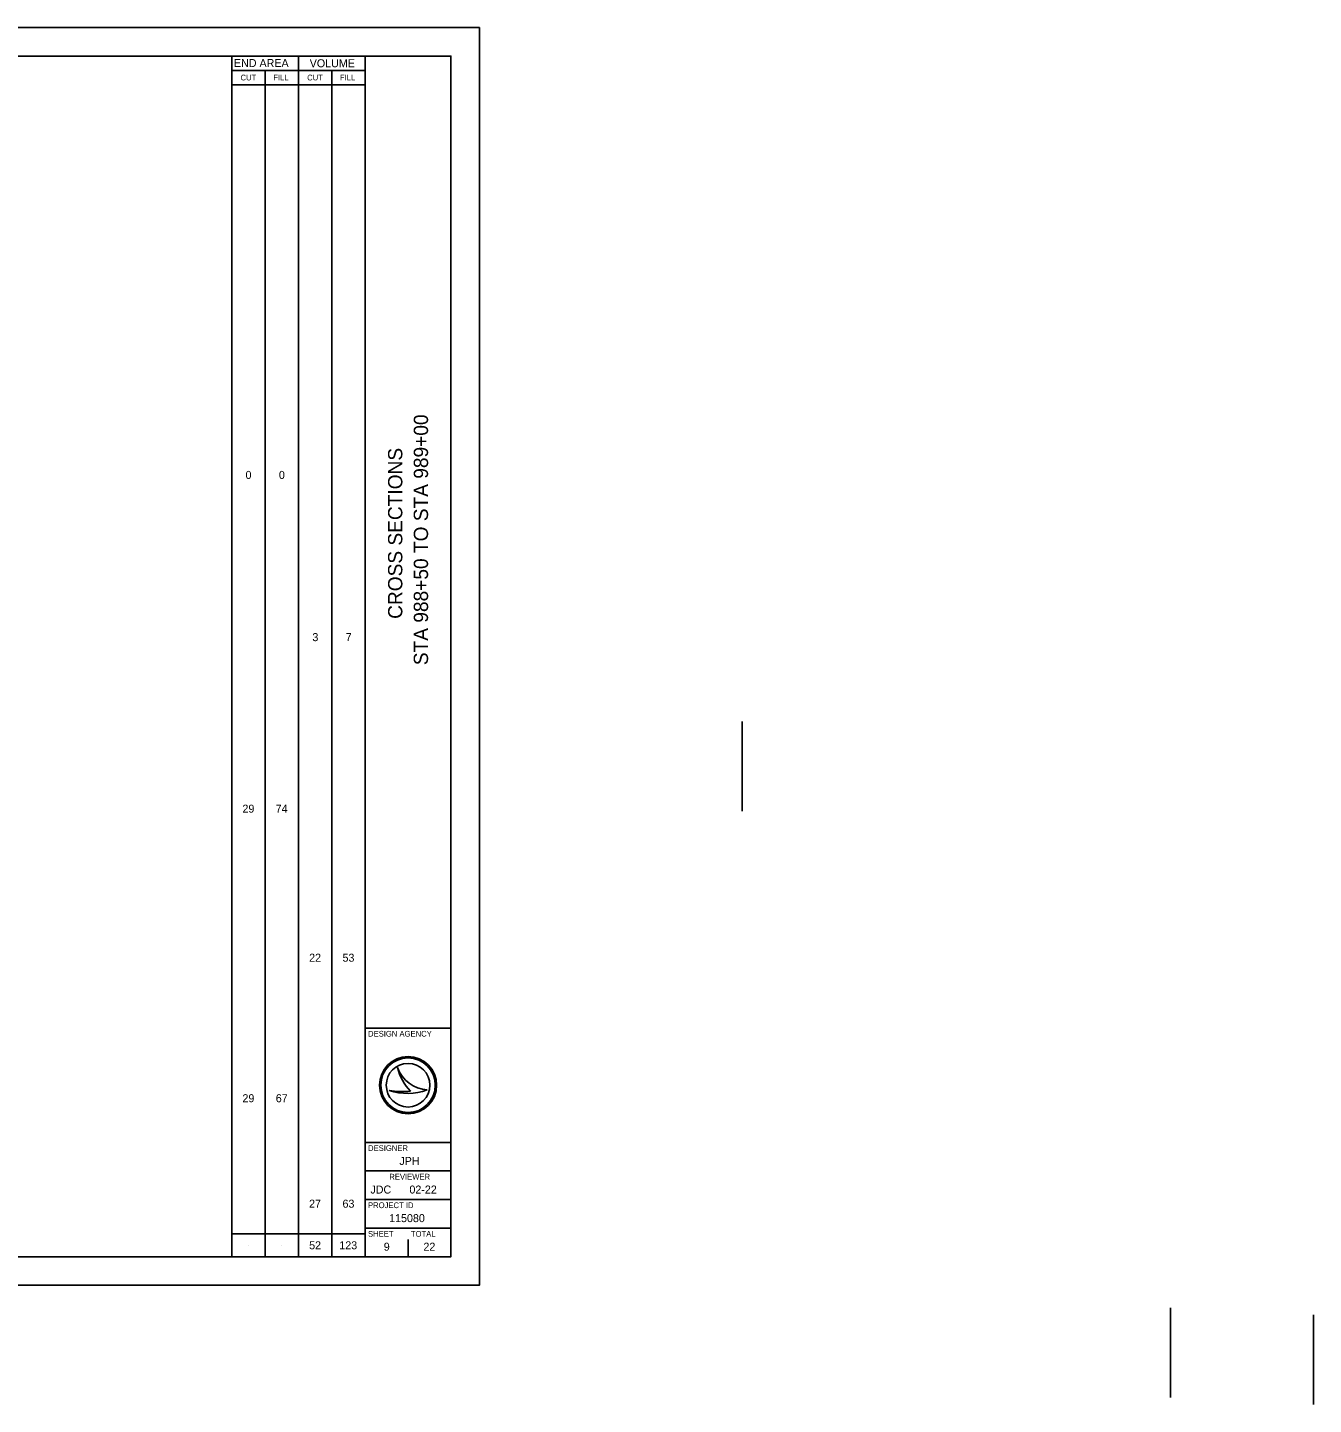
# Model space of a CAD drawing. Extents: x -41 to 232, y -116 to 22.
# Drawn here: x 26.09 to 48.59, y -2.08 to 22 of the extents above; entities that cross this region are included whole.
import ezdxf

# ---------------------------------------------------------------- set-up
doc = ezdxf.new("R2010")
doc.units = 0
for name, color, linetype in [('DT_X_Contour_Major', 7, 'Continuous'), ('DT_X_Contour_Minor', 7, 'Continuous'), ('DT_X_Contour_Text', 7, 'Continuous'), ('SH_Border', 7, 'Continuous'), ('SH_Cut_Line', 7, 'Continuous'), ('SH_Data', 7, 'Continuous'), ('SV_X_Break_Lines', 7, 'Continuous')]:
    doc.layers.add(name, color=color, linetype=linetype)

msp = doc.modelspace()

# ---------------------------------------------------------------- linework, layer by layer
at = {"layer": 'DT_X_Contour_Major'}
msp.add_line((38.594, 8.291), (38.594, 9.859), dxfattribs=at)
at = {"layer": 'DT_X_Contour_Minor'}
msp.add_line((46.094, -1.961), (46.094, -0.393), dxfattribs=at)
at = {"layer": 'DT_X_Contour_Text'}
msp.add_line((48.594, -2.084), (48.594, -0.516), dxfattribs=at)
at = {"layer": 'SH_Border'}
for p, q in [((32, 0.5), (32, 21.5)), ((32, 4.5), (33.5, 4.5)), ((32, 2.5), (33.5, 2.5)), ((32, 2), (33.5, 2)), ((32, 1.5), (33.5, 1.5)), ((32, 1), (33.5, 1))]:
    msp.add_line(p, q, dxfattribs=at)
msp.add_lwpolyline([(1.5, 21.5), (33.5, 21.5), (33.5, 0.5), (1.5, 0.5)], close=True, dxfattribs=at)
at = {"layer": 'SH_Cut_Line'}
msp.add_lwpolyline([(0, 0), (34, 0), (34, 22), (0, 22)], close=True, dxfattribs=at)
at = {"layer": 'SH_Data'}
for p, q in [((29.666, 0.5), (29.666, 21.5)), ((30.833, 0.5), (30.833, 21.5)), ((29.666, 21.25), (32, 21.25)), ((30.25, 0.5), (30.25, 21.25)), ((31.417, 0.5), (31.417, 21.25)), ((29.666, 21), (32, 21)), ((32.567, 3.81), (32.567, 3.81)), ((32.417, 3.41), (32.417, 3.41)), ((32.75, 3.5), (32.75, 3.5)), ((33.087, 3.419), (33.087, 3.419)), ((29.666, 0.9), (32, 0.9)), ((32.75, 0.5), (32.75, 0.8)), ((29.958, 0.7), (29.958, 0.7)), ((30.542, 0.7), (30.542, 0.7)), ((31.125, 0.7), (31.125, 0.7)), ((31.708, 0.7), (31.708, 0.7)), ((32.375, 0.675), (32.375, 0.675))]:
    msp.add_line(p, q, dxfattribs=at)
for radius in [0.5, 0.477, 0.477, 0.382]:
    msp.add_circle((32.75, 3.5), radius, dxfattribs=at)
for centre, radius, start, end in [((33.116, 3.998), 0.58, 198.9257, 198.9319), ((33.347, 3.97), 0.796, 191.6379, 191.6421), ((33.116, 3.998), 0.58, 198.9319, 267.1657), ((33.347, 3.97), 0.796, 191.6421, 226.0947), ((32.739, 4.37), 1.013, 251.4576, 290.0832), ((32.648, 4.654), 1.266, 259.4964, 259.4995), ((32.739, 4.37), 1.013, 251.4527, 251.4576), ((32.648, 4.654), 1.266, 259.4995, 276.6672)]:
    msp.add_arc(centre, radius, start, end, dxfattribs=at)

# ---------------------------------------------------------------- texts
for s, height, p in [('END AREA', 0.14, (29.703, 21.309)), ('VOLUME', 0.14, (31.029, 21.305)), ('CUT', 0.1, (29.819, 21.075)), ('FILL', 0.1, (30.391, 21.075)), ('CUT', 0.1, (30.985, 21.075)), ('FILL', 0.1, (31.557, 21.075)), ('DESIGN AGENCY', 0.1, (32.05, 4.35)), ('DESIGNER', 0.1, (32.05, 2.35)), ('JPH', 0.14, (32.598, 2.105)), ('REVIEWER', 0.1, (32.422, 1.85)), ('JDC', 0.14, (32.091, 1.605)), ('02-22', 0.14, (32.774, 1.605)), ('PROJECT ID', 0.1, (32.05, 1.35)), ('115080', 0.14, (32.419, 1.105)), ('SHEET', 0.1, (32.05, 0.85)), ('9', 0.14, (32.325, 0.605)), ('TOTAL', 0.1, (32.8, 0.85)), ('22', 0.14, (33.019, 0.605))]:
    msp.add_text(s, height=height, dxfattribs=at).set_placement(p)
for s, p in [('STA 988+50 TO STA 989+00', (33.1, 10.847)), ('CROSS SECTIONS', (32.65, 11.657))]:
    msp.add_text(s, height=0.25, rotation=90, dxfattribs=at).set_placement(p)
at = {"layer": 'SV_X_Break_Lines'}
for s, p in [('0', (29.906, 14.105)), ('0', (30.49, 14.105)), ('3', (31.076, 11.267)), ('7', (31.658, 11.267)), ('29', (29.852, 8.267)), ('74', (30.433, 8.267)), ('22', (31.019, 5.66)), ('53', (31.603, 5.66)), ('29', (29.852, 3.202)), ('67', (30.435, 3.202)), ('27', (31.018, 1.358)), ('63', (31.603, 1.358)), ('52', (31.019, 0.63)), ('123', (31.547, 0.63))]:
    msp.add_text(s, height=0.14, dxfattribs=at).set_placement(p)

doc.saveas('drawing.dxf')
